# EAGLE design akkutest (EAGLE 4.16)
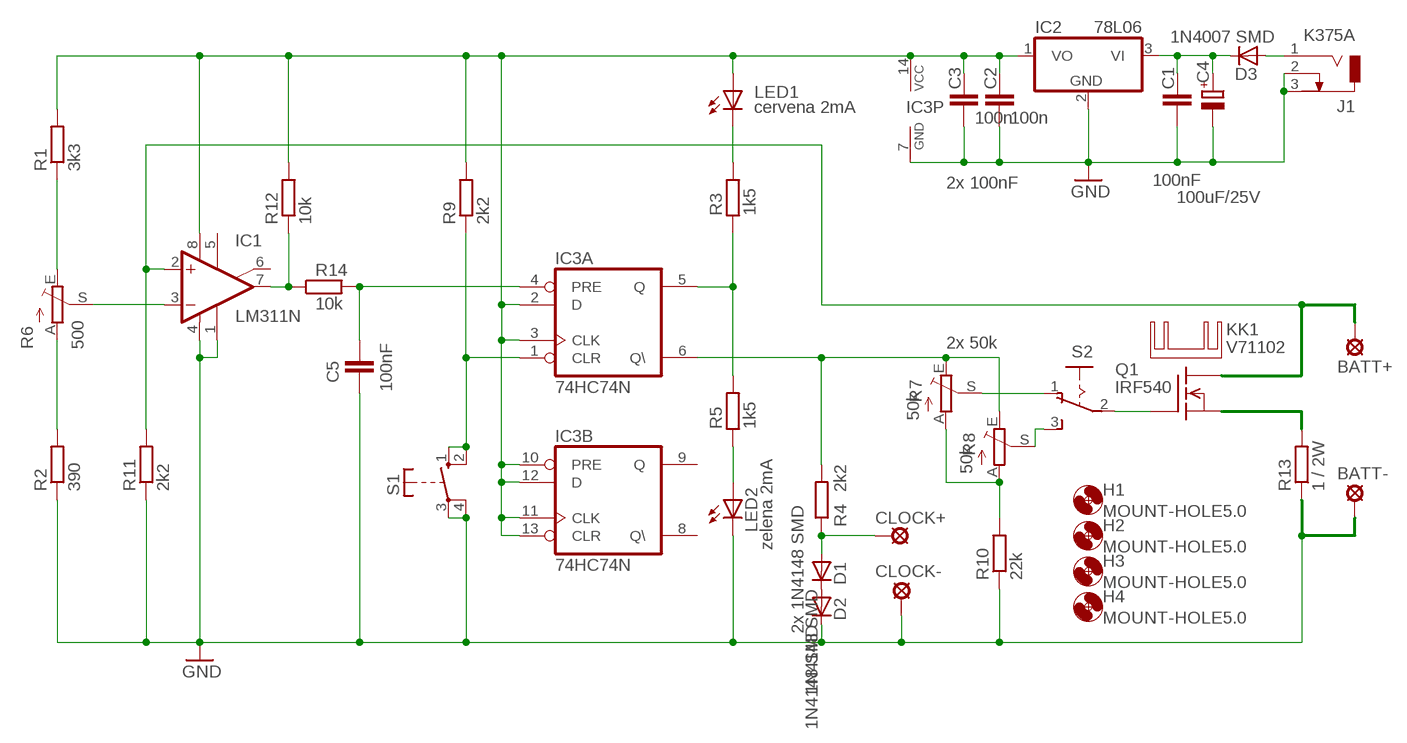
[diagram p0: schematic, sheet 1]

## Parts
BATT+  SE14  [SE14]
BATT-  SE14  [SE14]
C1  100nF  C-EUC1206  [C1206]
C2  100n  C-EUC1206  [C1206]
C3  100n  C-EUC1206  [C1206]
C4  100uF/25V  CPOL-EUE2.5-7  [E2,5-7]
C5  100nF  C-EUC1206  [C1206]
CLOCK+  LSP10  [LSP10]
CLOCK-  LSP10  [LSP10]
D1  1N4148 SMD  DIODE-MINIMELF  [MINIMELF]
D2  1N4148 SMD  DIODE-MINIMELF  [MINIMELF]
D3  1N4007 SMD  DIODE-MELF-MLL41  [MELF-MLL41]
H1  MOUNT-HOLE5.0  [5,0]
H2  MOUNT-HOLE5.0  [5,0]
H3  MOUNT-HOLE5.0  [5,0]
H4  MOUNT-HOLE5.0  [5,0]
IC1  LM311N  [DIL08]
IC2  78L06  7805L  [TO92]
IC3  74HC74N  [DIL14]
J1  K375A  DCJ0202  [DCJ0202]
KK1  V71102  D0A-L  [D02A-L]
LED1  cervena 2mA  LED5MM  [LED5MM]
LED2  zelena 2mA  LED5MM  [LED5MM]
Q1  IRF540  [TO220]
R1  3k3  R-EU_R1206  [R1206]
R2  390  R-EU_R1206  [R1206]
R3  1k5  R-EU_R1206  [R1206]
R4  2k2  R-EU_R1206  [R1206]
R5  1k5  R-EU_R1206  [R1206]
R6  500  TRIM_EU-CA9V  [CA9V]
R7  50k  TRIM_EU-CA9V  [CA9V]
R8  50k  TRIM_EU-CA9V  [CA9V]
R9  2k2  R-EU_R1206  [R1206]
R10  22k  R-EU_R1206  [R1206]
R11  2k2  R-EU_R1206  [R1206]
R12  10k  R-EU_R1206  [R1206]
R13  1 / 2W  R-EU_0414/15  [0414/15]
R14  10k  R-EU_R1206  [R1206]
S1  DT6  [DT6]
S2  255SB  [255SB]

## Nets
+5V: C2.1 C3.1 IC1.8(V+) IC2.1(VO) IC3.2(A:D) IC3.3(A:CLK) IC3.10(B:PRE) IC3.11(B:CLK) IC3.12(B:D) IC3.13(B:CLR) IC3.14(P:VCC) LED1.A R1.2 R9.2 R12.2
DISCHG: BATT+.MP IC1.2(+IN) Q1.2(D) R11.2
GND: BATT-.MP C1.2 C2.2 C3.2 C4.- C5.2 CLOCK-.MP D2.C IC1.1(GND) IC1.4(V-) IC2.2(GND) IC3.7(P:GND) J1.2 J1.3 LED2.K(C) R2.1 R10.1 R11.1 R13.1 S1.3(P) S1.4(P)
N$1: LED1.K(C) R3.2
N$2: CLOCK+.MP D1.A R4.1
N$3: IC3.5(A:Q) R3.1 R5.2
N$4: R2.2 R6.A
N$5: R1.1 R6.E
N$6: D1.C D2.A
N$7: IC1.3(-IN) R6.S
N$8: IC3.6(A:Q\) R4.2 R7.E R8.E
N$9: IC1.7(OUT) R12.1 R14.1
N$10: R7.A R8.A R10.2
N$11: C1.1 C4.+ D3.C IC2.3(VI)
N$12: R7.S S2.1(O)
N$13: R8.S S2.3(S)
N$14: Q1.1(G) S2.2(P)
N$15: IC3.1(A:CLR) R9.1 S1.1(S) S1.2(S)
N$16: D3.A J1.1
N$17: LED2.A R5.1
N$18: Q1.3(S) R13.2
N$19: C5.1 IC3.4(A:PRE) R14.2
Unconnected: IC1.5(ON) IC1.6(ON/STR) IC3.8(B:Q\) IC3.9(B:Q)

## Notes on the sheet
- 2x 100nF
- 2x 50k
- 2x 1N4148 SMD

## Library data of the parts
BATT+ BATT- = solpad:SE14: SOLDER PAD
C1-C3 C5 = rcl:C-EU: CAPACITOR, European symbol
C4 = rcl:CPOL-EU: POLARIZED CAPACITOR, European symbol
CLOCK+ CLOCK- = solpad:LSP10: SOLDER PAD
D1-D3 = diode:DIODE-: DIODE
H1-H4 = holes:MOUNT-HOLE: MOUNTING HOLE with drill center marker
IC1 = linear:LM311: COMPARATOR
IC2 = linear:78*: Positive VOLTAGE REGULATOR Source: http://cache.national.com/ds/LM/LM78L05.pdf http://www.fairchildsemi.com/ds/LM/LM7805.pdf
IC3 = 74xx-eu:74*74: Dual D type positive edge triggered FLIP FLOP, preset and clear
J1 = con-jack:DCJ0202: DC POWER JACK Source: DCJ0202.pdf
KK1 = heatsink:D0A-L: HEATSINK
LED1 LED2 = led:LED: LED
Q1 = transistor-fet:IRF540: N-Channel Enhancement MOSFET (HEXFET); 100V; 28A; 0,077Ohm
R1-R5 R9-R14 = rcl:R-EU_: RESISTOR, European symbol
R6-R8 = pot:TRIM_EU-: POTENTIOMETER
S1 = switch-misc:DT: ITT SWITCH
S2 = switch:255SB: SLIDING SWITCH distributor Buerklin, 11G810

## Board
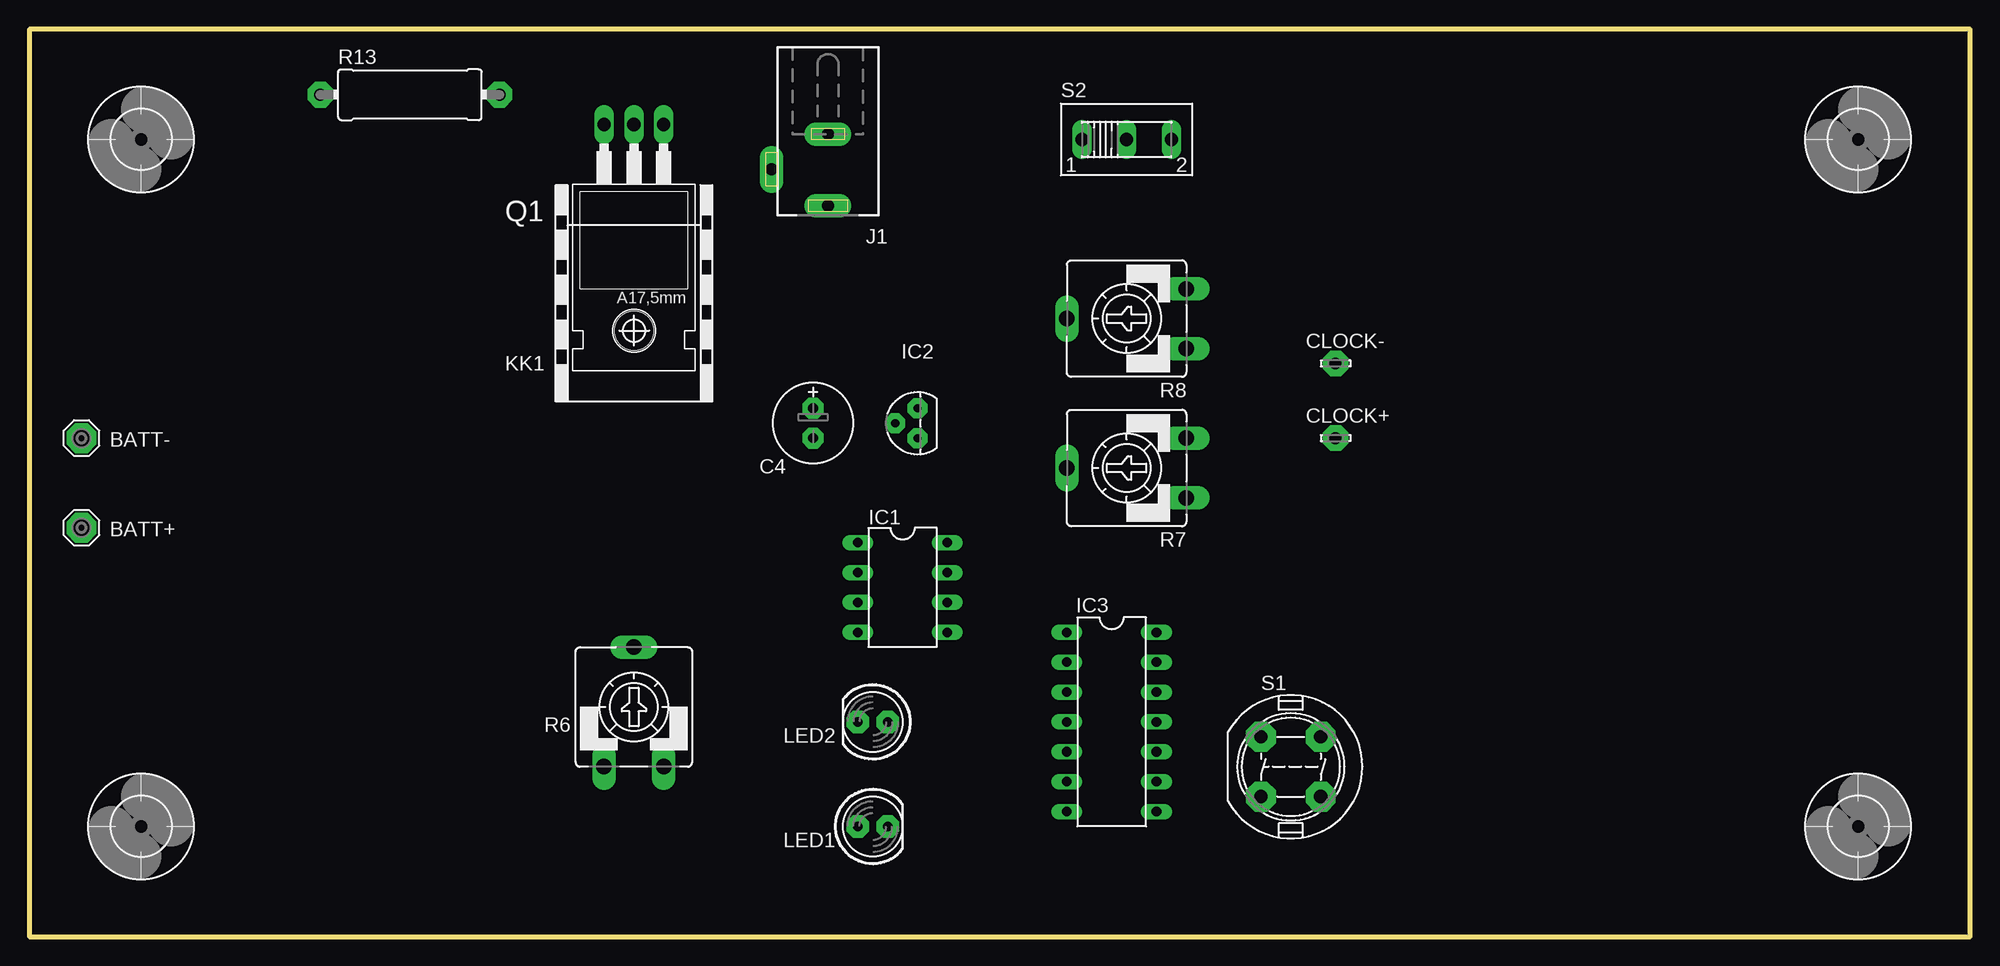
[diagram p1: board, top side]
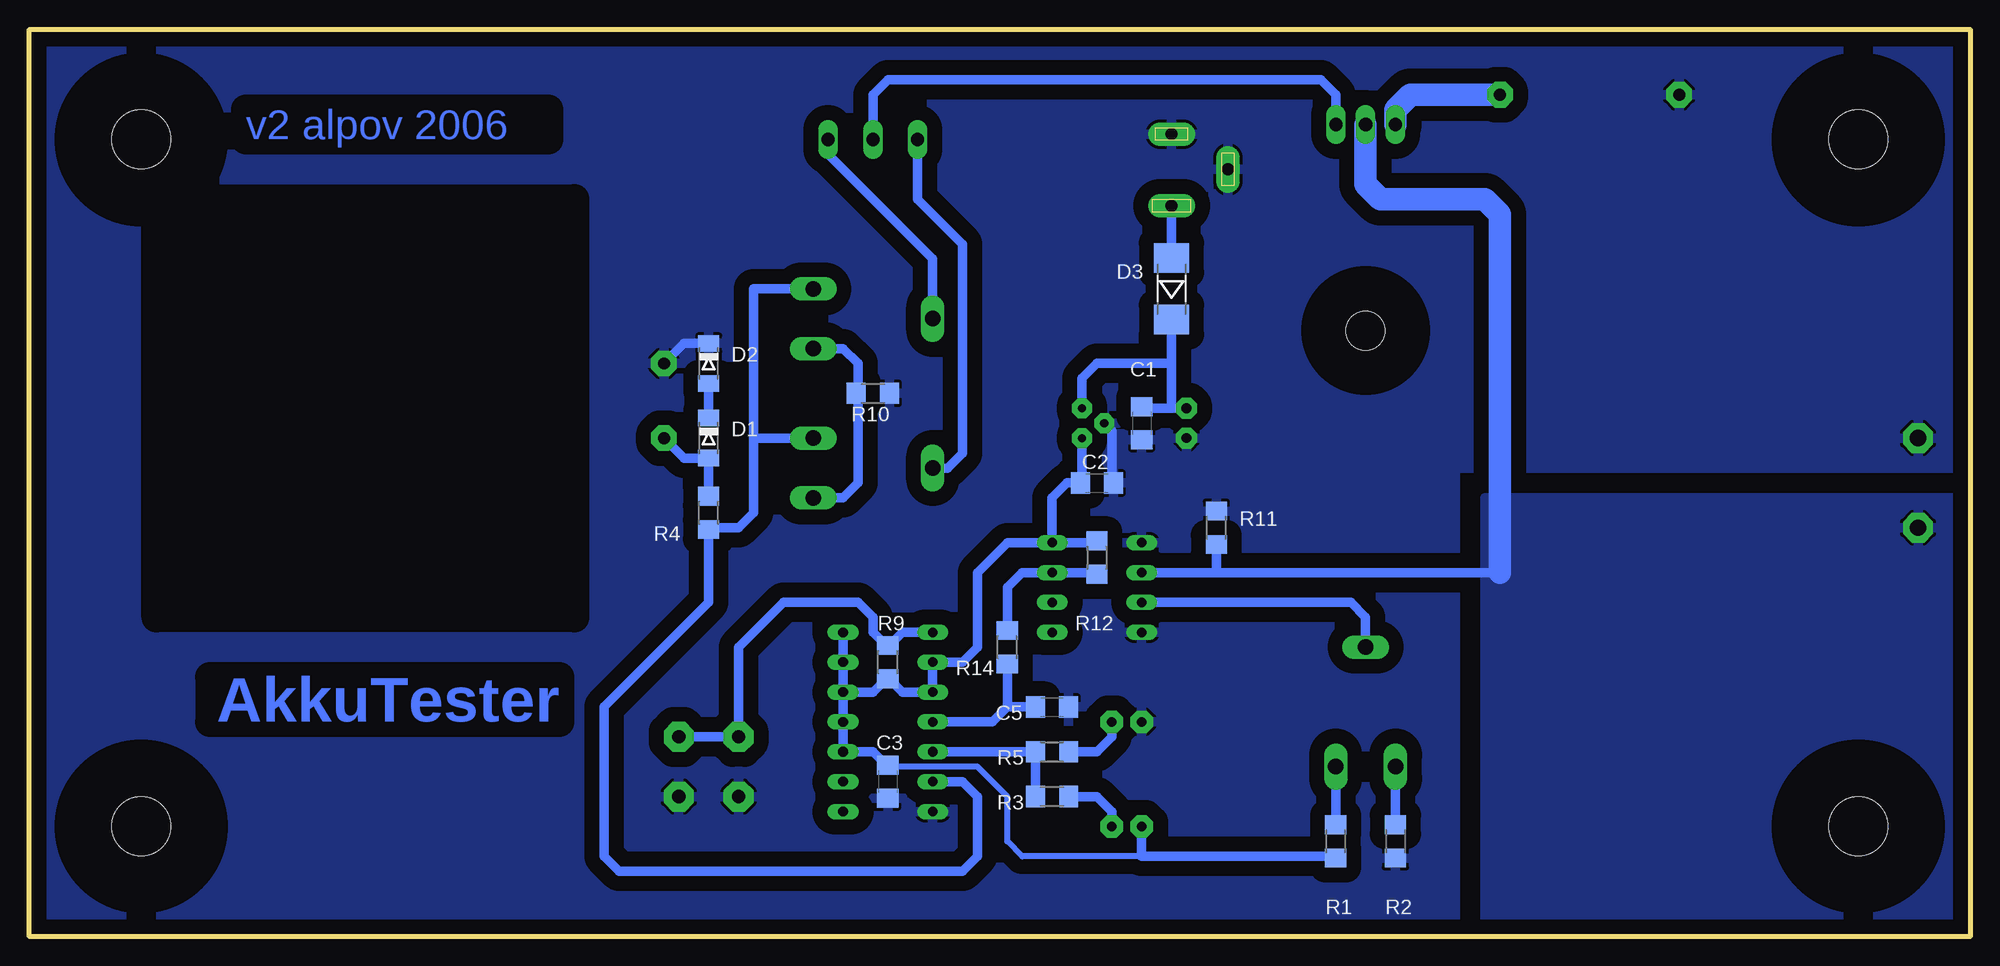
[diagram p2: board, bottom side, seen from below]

Size 165.08 x 77.14 mm. Coordinates in mm from the lower left corner, seen from the top.
Outline: 165.08,77.14 0,77.14 0,0 165.08,0 165.08,77.14
Copper layers (1*16): Top 0.035mm / dielectric 1.5mm / Bottom 0.035mm
Design rules "default": minimum track width 10mil, minimum drill 24mil, track to track 8mil, track to pad 8mil, pad to pad 8mil, via to via 8mil, smd to smd 8mil, copper to edge 40mil, drill to drill 8mil, minimum pad ring 10mil, minimum via ring 8mil, stop-mask expansion 4mil, vias tented up to drill 0mil, thermal gap 10mil
bRestrict: area 118.7,27.1 to 154.3,62.7

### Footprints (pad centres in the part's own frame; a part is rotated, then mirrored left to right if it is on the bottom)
SE14 = drill 1.397 pad 2.54 octagon: MP 0,0
C1206 = smd 1.6 x 1.8: 1 -1.4,0; 2 1.4,0
E2,5-7 = drill 0.813 pad 1.778 octagon: + -1.27,0; - 1.27,0
LSP10 = drill 1.016 pad 2.159 octagon: MP 0,0
MINIMELF = smd 1.4 x 1.8: A 1.7,0; C -1.7,0
MELF-MLL41 = smd 2.5 x 3: A 2.625,0; C -2.625,0
5,0 = hole 5: 0,0
DIL08 = drill 0.813 long: 1 -3.81,-3.81; 2 -1.27,-3.81; 3 1.27,-3.81; 4 3.81,-3.81; 5 3.81,3.81; 6 1.27,3.81; 7 -1.27,3.81; 8 -3.81,3.81
TO92 = drill 0.7 pad 1.676 octagon: 1 -1.27,0; 2 0,1.905; 3 1.27,0
DIL14 = drill 0.813 long: 1 -7.62,-3.81; 2 -5.08,-3.81; 3 -2.54,-3.81; 4 0,-3.81; 5 2.54,-3.81; 6 5.08,-3.81; 7 7.62,-3.81; 8 7.62,3.81; 9 5.08,3.81; 10 2.54,3.81; 11 0,3.81; 12 -2.54,3.81; 13 -5.08,3.81; 14 -7.62,3.81
DCJ0202 = drill 1 pad 2 long: 1 0,3.1; 2 4.8,0; 3 0,-3
LED5MM = drill 0.813 pad 1.93 octagon: A -1.27,0; K 1.27,0
TO220 = drill 1.118 long: 1 -2.54,-6.35; 2 0,-6.35; 3 2.54,-6.35 | hole 3.302: 0,11.176
R1206 = smd 1.6 x 1.803: 1 -1.422,0; 2 1.422,0
CA9V = drill 1.321 long: A -2.54,-5.08; E 2.54,-5.08; S 0,5.08
0414/15 = drill 1.016 pad 2.184 octagon: 1 -7.62,0; 2 7.62,0
DT6 = drill 1.118 pad 2.54 octagon: 1 -2.54,2.54; 2 2.54,2.54; 3 2.54,-2.54; 4 -2.54,-2.54
255SB = drill 1.118 long: 1 -3.81,0; 2 0,0; 3 3.81,0

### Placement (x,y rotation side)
BATT+  4.43,34.76 180 top
BATT-  4.43,42.38 180 top
C1  70.47,43.65 270 bottom
C2  74.28,38.57 0 bottom
C3  92.06,13.17 270 bottom
C4  66.66,43.65 270 top
C5  78.09,19.52 0 bottom
CLOCK+  111.11,42.38 0 top
CLOCK-  111.11,48.73 0 top
D1  107.3,42.38 270 bottom
D2  107.3,48.73 270 bottom
D3  67.93,55.08 90 bottom
H1  155.56,67.78 180 top
H2  9.51,67.78 180 top
H3  155.56,9.36 180 top
H4  9.51,9.36 180 top
IC1  74.28,29.68 270 top
IC2  75.55,43.65 90 top
IC3  92.06,18.25 270 top
J1  67.93,65.24 180 top
KK1  51.42,56.98 90 top
LED1  71.74,9.36 0 top
LED2  71.74,18.25 180 top
Q1  51.42,62.7 180 top
R1  53.96,8.09 270 bottom
R2  48.88,8.09 90 bottom
R3  78.09,11.9 0 bottom
R4  107.3,36.03 270 bottom
R5  78.09,15.71 180 bottom
R6  51.42,19.52 0 top
R7  93.33,39.84 90 top
R8  93.33,52.54 90 top
R9  92.06,23.33 270 bottom
R10  93.33,46.19 180 bottom
R11  64.12,34.76 270 bottom
R12  74.28,32.22 90 bottom
R13  32.37,71.59 0 top
R14  81.9,24.6 270 bottom
S1  107.3,14.44 0 top
S2  93.33,67.78 0 top

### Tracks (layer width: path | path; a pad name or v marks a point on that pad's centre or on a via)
+5V
  Bottom 0.5: 92.06,14.44 84.44,14.44 81.9,11.9 81.9,8.09 80.63,6.82 70.47,6.82
  Bottom 0.813: IC3.14 IC3.13 IC3.12 | IC3.12 IC3.11 IC3.10 93.33,15.71 92.06,14.44 C3.1 | IC3.12 93.33,20.79 92.21,21.91 R9.2 91.91,21.91 90.79,20.79 IC3.3 IC3.2 85.71,23.33 84.44,24.6 84.44,30.95 81.9,33.49 IC1.8 | IC2.1 75.55,38.57 C2.1 76.82,38.57 78.09,37.3 IC1.8 | R1.2 53.96,6.82 70.47,6.82 LED1.A | R12.2 74.28,33.49 IC1.8
DISCHG
  Bottom 0.813: 39.99,30.95 64.12,30.95 | 64.12,30.95 IC1.2 | 64.12,30.95 R11.2
  Bottom 1.93: Q1.2 51.42,63.97 50.15,62.7 41.26,62.7 39.99,61.43 39.99,30.95
  pour Bottom (isolate 1.27): 41.26,37.3 41.26,0.47 0.62,0.47 0.62,37.3
GND
  Bottom 0.813: CLOCK-.MP 109.41,50.43 D2.C 106.87,50.43 | R10.1 92.06,46.19 | C3.2 92.06,11.9 | C2.2 73.01,38.57 73.01,43.02 IC2.2
  pour Bottom (isolate 1.27): 164.45,0.47 164.45,76.67 0.62,76.67 0.62,39.84 43.8,39.84 43.8,0.47
N$1
  Bottom 0.813: LED1.K 73.01,10.63 74.28,11.9 R3.2 76.82,11.9
N$2
  Bottom 0.813: R4.1 D1.A 109.41,40.68 CLOCK+.MP
N$3
  Bottom 0.813: R3.1 79.36,11.9 79.51,12.05 R5.2 | R5.2 79.36,15.71 | R5.2 IC3.5
N$4
  Bottom 0.813: 48.88,9.36 R2.2 R6.A
N$5
  Bottom 0.813: 53.96,9.36 R1.1 R6.E
N$6
  Bottom 0.813: D1.C D2.A
N$7
  Bottom 0.813: R6.S 51.42,27.14 52.69,28.41 IC1.3
N$8
  Bottom 0.813: 103.49,42.38 103.49,36.03 104.76,34.76 107.3,34.76 | 103.49,42.38 R7.E | R8.E 103.49,55.08 103.49,42.38 | IC3.6 85.71,13.17 84.44,11.9 84.44,6.82 85.71,5.55 114.92,5.55 116.19,6.82 116.19,19.52 107.3,28.41 107.3,34.76 | 107.3,34.76 R4.2
N$9
  Bottom 0.813: R12.1 74.28,30.95 IC1.7 80.63,30.95 81.9,29.68 R14.1 81.9,25.87
N$10
  Bottom 0.813: R8.A 95.87,50 94.6,48.73 94.6,46.19 | R7.A 95.87,37.3 94.6,38.57 94.6,46.19 | 94.6,46.19 R10.2
N$11
  Bottom 0.813: C1.1 70.47,44.92 67.93,44.92 | C4.+ 67.93,44.92 | 67.93,44.92 67.93,48.73 | 67.93,48.73 D3.C | IC2.3 75.55,47.46 74.28,48.73 67.93,48.73
N$12
  Bottom 0.813: R7.S 86.98,39.84 85.71,41.11 85.71,58.89 89.52,62.7 S2.1
N$13
  Bottom 0.813: R8.S 88.25,57.62 97.14,66.51 S2.3
N$14
  Bottom 0.813: S2.2 93.33,71.59 92.06,72.86 55.23,72.86 53.96,71.59 Q1.1
N$15
  Bottom 0.813: IC3.1 90.79,25.87 92.06,24.6 R9.1 92.21,24.75 93.33,25.87 93.33,27.14 94.6,28.41 100.95,28.41 104.76,24.6 S1.1 S1.2
N$16
  Bottom 0.813: 67.93,60.16 D3.A J1.1
N$17
  Bottom 0.813: LED2.A 73.01,16.98 74.28,15.71 R5.1 76.82,15.71
N$18
  Bottom 1.93: Q1.3 48.88,70.32 47.61,71.59 R13.2
N$19
  Bottom 0.813: 81.9,19.52 83.17,18.25 IC3.4 | 79.36,19.52 C5.1 81.9,19.52 | 81.9,19.52 R14.2

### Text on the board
Bottom: v2 alpov 2006 | AkkuTester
